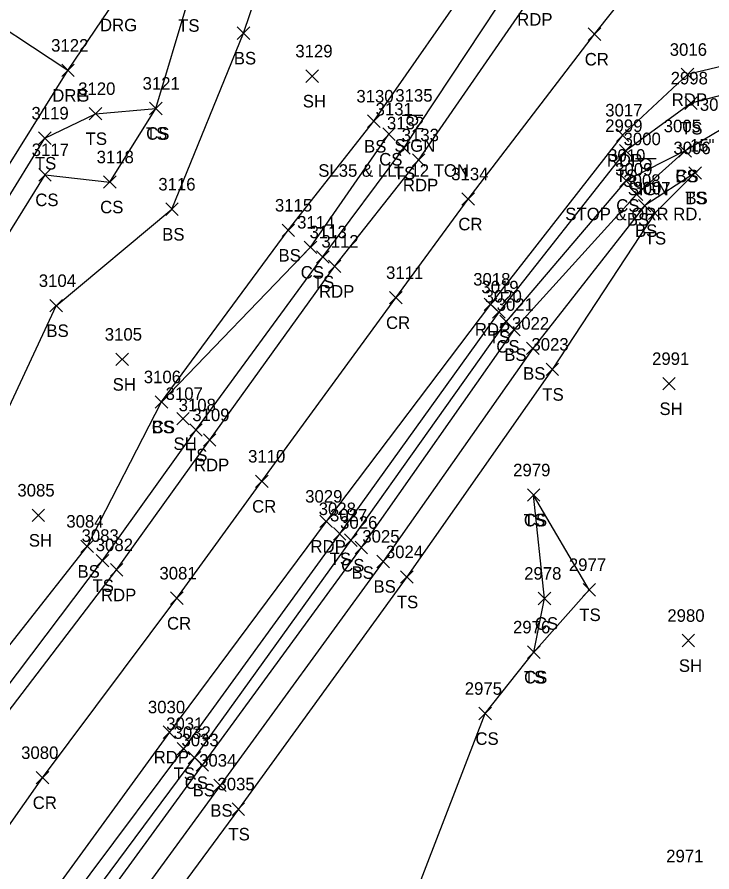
# Model space of a CAD drawing. Extents: x 1520648 to 1523413, y 732854 to 735518.
# Drawn here: x 1521785.1 to 1521896.1, y 733315.9 to 733452.5 of the extents above; entities that cross this region are included whole.
import ezdxf

# ---------------------------------------------------------------- set-up
doc = ezdxf.new("R2010")
doc.units = 0
for name, color, linetype in [('D_C', 7, 'Continuous'), ('L_A', 7, 'Continuous'), ('L_I', 7, 'Continuous'), ('L_TIC', 7, 'Continuous'), ('LELB', 7, 'Continuous'), ('P_A', 7, 'Continuous'), ('P_I', 7, 'Continuous'), ('P_TIC', 7, 'Continuous'), ('PET', 7, 'Continuous'), ('PRC', 7, 'Continuous'), ('R_A', 7, 'Continuous'), ('R_I', 7, 'Continuous'), ('R_TIC', 7, 'Continuous'), ('RDG', 7, 'Continuous'), ('RDP', 7, 'Continuous'), ('S_A', 7, 'Continuous'), ('S_C', 7, 'Continuous'), ('S_I', 7, 'Continuous'), ('SSGN', 7, 'Continuous')]:
    doc.layers.add(name, color=color, linetype=linetype)

msp = doc.modelspace()

# ---------------------------------------------------------------- linework, layer by layer
at = {"layer": 'L_TIC'}
for points in [[(1521820.29, 733448.95), (1521822.29, 733450.95)], [(1521822.29, 733448.95), (1521820.29, 733450.95)], [(1521831.26, 733442.08), (1521833.26, 733444.08)], [(1521833.26, 733442.08), (1521831.26, 733444.08)], [(1521891.77, 733437.76), (1521893.77, 733439.76)], [(1521893.77, 733437.76), (1521891.77, 733439.76)], [(1521796.65, 733436.08), (1521798.65, 733438.08)], [(1521798.65, 733436.08), (1521796.65, 733438.08)], [(1521806.29, 733436.92), (1521808.29, 733438.92)], [(1521808.29, 733436.92), (1521806.29, 733438.92)], [(1521806.29, 733436.92), (1521808.29, 733438.92)], [(1521808.29, 733436.92), (1521806.29, 733438.92)], [(1521841.09, 733434.87), (1521843.09, 733436.87)], [(1521843.09, 733434.87), (1521841.09, 733436.87)], [(1521788.55, 733432.16), (1521790.55, 733434.16)], [(1521790.55, 733432.16), (1521788.55, 733434.16)], [(1521843.51, 733432.8), (1521845.51, 733434.8)], [(1521845.51, 733432.8), (1521843.51, 733434.8)], [(1521845.88, 733430.59), (1521847.88, 733432.59)], [(1521847.88, 733430.59), (1521845.88, 733432.59)], [(1521881.33, 733430.16), (1521883.33, 733432.16)], [(1521883.33, 733430.16), (1521881.33, 733432.16)], [(1521890.82, 733430.12), (1521892.82, 733432.12)], [(1521892.82, 733430.12), (1521890.82, 733432.12)], [(1521890.82, 733430.12), (1521892.82, 733432.12)], [(1521892.82, 733430.12), (1521890.82, 733432.12)], [(1521788.58, 733426.31), (1521790.58, 733428.31)], [(1521790.58, 733426.31), (1521788.58, 733428.31)], [(1521892.42, 733426.61), (1521894.42, 733428.61)], [(1521894.42, 733426.61), (1521892.42, 733428.61)], [(1521892.42, 733426.61), (1521894.42, 733428.61)], [(1521894.42, 733426.61), (1521892.42, 733428.61)], [(1521798.94, 733425.16), (1521800.94, 733427.16)], [(1521800.94, 733425.16), (1521798.94, 733427.16)], [(1521881.38, 733425.41), (1521883.38, 733427.41)], [(1521883.38, 733425.41), (1521881.38, 733427.41)], [(1521883.07, 733423.19), (1521885.07, 733425.19)], [(1521885.07, 733423.19), (1521883.07, 733425.19)], [(1521884.37, 733421.39), (1521886.37, 733423.39)], [(1521886.37, 733421.39), (1521884.37, 733423.39)], [(1521808.85, 733420.81), (1521810.85, 733422.81)], [(1521810.85, 733420.81), (1521808.85, 733422.81)], [(1521885.97, 733420.18), (1521887.97, 733422.18)], [(1521887.97, 733420.18), (1521885.97, 733422.18)], [(1521827.43, 733417.45), (1521829.43, 733419.45)], [(1521829.43, 733417.45), (1521827.43, 733419.45)], [(1521830.98, 733414.73), (1521832.98, 733416.73)], [(1521832.98, 733414.73), (1521830.98, 733416.73)], [(1521832.96, 733413.18), (1521834.96, 733415.18)], [(1521834.96, 733413.18), (1521832.96, 733415.18)], [(1521790.35, 733405.4), (1521792.35, 733407.4)], [(1521792.35, 733405.4), (1521790.35, 733407.4)], [(1521861.06, 733404.38), (1521863.06, 733406.38)], [(1521863.06, 733404.38), (1521861.06, 733406.38)], [(1521862.22, 733402.9), (1521864.22, 733404.9)], [(1521864.22, 733402.9), (1521862.22, 733404.9)], [(1521863.49, 733401.58), (1521865.49, 733403.58)], [(1521865.49, 733401.58), (1521863.49, 733403.58)], [(1521866.5, 733398.58), (1521868.5, 733400.58)], [(1521868.5, 733398.58), (1521866.5, 733400.58)], [(1521800.89, 733396.82), (1521802.89, 733398.82)], [(1521802.89, 733396.82), (1521800.89, 733398.82)], [(1521869.61, 733395.22), (1521871.61, 733397.22)], [(1521871.61, 733395.22), (1521869.61, 733397.22)], [(1521888.24, 733392.93), (1521890.24, 733394.93)], [(1521890.24, 733392.93), (1521888.24, 733394.93)], [(1521807.18, 733390.02), (1521809.18, 733392.02)], [(1521809.18, 733390.02), (1521807.18, 733392.02)], [(1521807.18, 733390.02), (1521809.18, 733392.02)], [(1521809.18, 733390.02), (1521807.18, 733392.02)], [(1521810.61, 733387.35), (1521812.61, 733389.35)], [(1521812.61, 733387.35), (1521810.61, 733389.35)], [(1521812.69, 733385.53), (1521814.69, 733387.53)], [(1521814.69, 733385.53), (1521812.69, 733387.53)], [(1521866.62, 733375.14), (1521868.62, 733377.14)], [(1521868.62, 733375.14), (1521866.62, 733377.14)], [(1521866.62, 733375.14), (1521868.62, 733377.14)], [(1521868.62, 733375.14), (1521866.62, 733377.14)], [(1521787.5, 733371.91), (1521789.5, 733373.91)], [(1521789.5, 733371.91), (1521787.5, 733373.91)], [(1521835.63, 733368.94), (1521837.63, 733370.94)], [(1521837.63, 733368.94), (1521835.63, 733370.94)], [(1521837.43, 733367.93), (1521839.43, 733369.93)], [(1521839.43, 733367.93), (1521837.43, 733369.93)], [(1521795.31, 733366.94), (1521797.31, 733368.94)], [(1521797.31, 733366.94), (1521795.31, 733368.94)], [(1521839.1, 733366.76), (1521841.1, 733368.76)], [(1521841.1, 733366.76), (1521839.1, 733368.76)], [(1521797.75, 733364.67), (1521799.75, 733366.67)], [(1521799.75, 733364.67), (1521797.75, 733366.67)], [(1521842.6, 733364.54), (1521844.6, 733366.54)], [(1521844.6, 733364.54), (1521842.6, 733366.54)], [(1521846.36, 733362.06), (1521848.36, 733364.06)], [(1521848.36, 733362.06), (1521846.36, 733364.06)], [(1521875.51, 733360.01), (1521877.51, 733362.01)], [(1521877.51, 733360.01), (1521875.51, 733362.01)], [(1521868.37, 733358.62), (1521870.37, 733360.62)], [(1521870.37, 733358.62), (1521868.37, 733360.62)], [(1521891.33, 733351.89), (1521893.33, 733353.89)], [(1521893.33, 733351.89), (1521891.33, 733353.89)], [(1521866.65, 733350.04), (1521868.65, 733352.04)], [(1521868.65, 733350.04), (1521866.65, 733352.04)], [(1521866.65, 733350.04), (1521868.65, 733352.04)], [(1521868.65, 733350.04), (1521866.65, 733352.04)], [(1521858.88, 733340.23), (1521860.88, 733342.23)], [(1521860.88, 733340.23), (1521858.88, 733342.23)], [(1521810.7, 733334.61), (1521812.7, 733336.61)], [(1521812.7, 733334.61), (1521810.7, 733336.61)], [(1521812.45, 733333.19), (1521814.45, 733335.19)], [(1521814.45, 733333.19), (1521812.45, 733335.19)], [(1521813.7, 733332), (1521815.7, 733334)], [(1521815.7, 733332), (1521813.7, 733334)], [(1521816.53, 733328.75), (1521818.53, 733330.75)], [(1521818.53, 733328.75), (1521816.53, 733330.75)], [(1521819.46, 733324.96), (1521821.46, 733326.96)], [(1521821.46, 733324.96), (1521819.46, 733326.96)]]:
    msp.add_lwpolyline(points, dxfattribs=at)
at = {"layer": 'LELB'}
for points in [[(1521759.01, 733350.84), (1521778.84, 733379.61), (1521791.35, 733406.4), (1521809.85, 733421.81), (1521821.29, 733449.95), (1521829.42, 733474.04), (1521816.98, 733499.02), (1521803.61, 733521.39), (1521760.13, 733541.49), (1521753.02, 733560.88), (1521736.69, 733577.42), (1521715.31, 733596.64)], [(1521749.24, 733355.76), (1521768.57, 733384.54), (1521778.63, 733397.02), (1521778.03, 733414.53), (1521789.55, 733433.16), (1521797.65, 733437.08), (1521807.29, 733437.92), (1521812.43, 733455.17), (1521816.31, 733477.33), (1521808.57, 733496.49), (1521793.28, 733514.64), (1521756.08, 733535.47), (1521746.24, 733557.11), (1521726.08, 733570.55), (1521703.63, 733583.19)], [(1521759.15, 733317.04), (1521772.09, 733331.62), (1521778.42, 733338.78), (1521798.75, 733365.67), (1521813.69, 733386.53), (1521833.96, 733414.18), (1521846.88, 733431.59), (1521864.41, 733458.07), (1521876.44, 733476.09), (1521887.28, 733496.86), (1521887.61, 733499.46), (1521888.35, 733509.55), (1521886.12, 733515.05), (1521875.14, 733547.35)], [(1521745.22, 733320.11), (1521742.07, 733329.87), (1521753.4, 733325.06), (1521769.53, 733333.34), (1521775.51, 733341.53), (1521796.31, 733367.94), (1521808.18, 733391.02), (1521828.43, 733418.45), (1521842.09, 733435.87), (1521859.18, 733460.44), (1521868.01, 733480.25), (1521878.13, 733498.03), (1521883.64, 733498.41), (1521879.84, 733511.18), (1521868.37, 733545.03)], [(1521968.22, 732870.86), (1521967.33, 732923.17), (1521965.89, 732967.63), (1521966.81, 733022.76), (1521968.92, 733067.53), (1521967.76, 733107.86), (1521967.59, 733152.46), (1521963.2, 733196.23), (1521957.56, 733240.65), (1521950.49, 733284.14), (1521942.81, 733326), (1521935.57, 733358.13), (1521922.67, 733395.52), (1521912.69, 733424.26), (1521908.68, 733436.25), (1521904.92, 733439.85), (1521900.99, 733440.9), (1521892.77, 733438.76), (1521882.33, 733431.16), (1521862.06, 733405.38), (1521836.63, 733369.94), (1521811.7, 733335.61), (1521781.71, 733295.53)], [(1521778.63, 733397.02), (1521780.75, 733413.12), (1521789.58, 733427.31), (1521799.94, 733426.16), (1521807.29, 733437.92)], [(1521949.65, 732892.14), (1521943.39, 732922.28), (1521945.76, 732969.81), (1521946.37, 733022.02), (1521949.39, 733069.39), (1521949.05, 733107.25), (1521954.07, 733151.48), (1521948.09, 733195.39), (1521946.43, 733238.1), (1521937.33, 733283.09), (1521933.08, 733323.42), (1521926.44, 733357.1), (1521915.28, 733394.28), (1521907.45, 733416.63), (1521900.78, 733431.27), (1521903.17, 733437.88), (1521902.02, 733437.98), (1521897.59, 733434.54), (1521891.82, 733431.12), (1521884.07, 733424.19), (1521864.49, 733402.58), (1521840.1, 733367.76), (1521814.7, 733333), (1521785.26, 733292.58)], [(1521808.18, 733391.02), (1521831.98, 733415.73), (1521844.51, 733433.8)], [(1521891.82, 733431.12), (1521882.38, 733426.41), (1521863.22, 733403.9), (1521838.43, 733368.93), (1521813.45, 733334.19), (1521783.62, 733294.05)], [(1521893.42, 733427.61), (1521885.37, 733422.39), (1521867.5, 733399.58), (1521843.6, 733365.54), (1521817.53, 733329.75), (1521788.72, 733290.22)], [(1521893.42, 733427.61), (1521886.97, 733421.18), (1521870.61, 733396.22), (1521847.36, 733363.06), (1521820.46, 733325.96), (1521793.78, 733289.79)], [(1521841.16, 733284.19), (1521847.31, 733308.65), (1521859.88, 733341.23), (1521867.65, 733351.04), (1521869.37, 733359.62), (1521867.62, 733376.14)], [(1521867.65, 733351.04), (1521876.51, 733361.01), (1521867.62, 733376.14)]]:
    msp.add_lwpolyline(points, dxfattribs=at)
at = {"layer": 'P_TIC'}
for points in [[(1521876.35, 733448.78), (1521878.35, 733450.78)], [(1521878.35, 733448.78), (1521876.35, 733450.78)], [(1521891.19, 733442.33), (1521893.19, 733444.33)], [(1521893.19, 733442.33), (1521891.19, 733444.33)], [(1521880.84, 733432.64), (1521882.84, 733434.64)], [(1521882.84, 733432.64), (1521880.84, 733434.64)], [(1521848.25, 733428.67), (1521850.25, 733430.67)], [(1521850.25, 733428.67), (1521848.25, 733430.67)], [(1521856.16, 733422.44), (1521858.16, 733424.44)], [(1521858.16, 733422.44), (1521856.16, 733424.44)], [(1521834.85, 733411.69), (1521836.85, 733413.69)], [(1521836.85, 733411.69), (1521834.85, 733413.69)], [(1521844.61, 733406.68), (1521846.61, 733408.68)], [(1521846.61, 733406.68), (1521844.61, 733408.68)], [(1521859.74, 733405.62), (1521861.74, 733407.62)], [(1521861.74, 733405.62), (1521859.74, 733407.62)], [(1521814.88, 733383.95), (1521816.88, 733385.95)], [(1521816.88, 733383.95), (1521814.88, 733385.95)], [(1521823.22, 733377.34), (1521825.22, 733379.34)], [(1521825.22, 733377.34), (1521823.22, 733379.34)], [(1521833.48, 733370.94), (1521835.48, 733372.94)], [(1521835.48, 733370.94), (1521833.48, 733372.94)], [(1521800.02, 733363.18), (1521802.02, 733365.18)], [(1521802.02, 733363.18), (1521800.02, 733365.18)], [(1521809.63, 733358.66), (1521811.63, 733360.66)], [(1521811.63, 733358.66), (1521809.63, 733360.66)], [(1521808.44, 733337.27), (1521810.44, 733339.27)], [(1521810.44, 733337.27), (1521808.44, 733339.27)], [(1521788.18, 733329.98), (1521790.18, 733331.98)], [(1521790.18, 733329.98), (1521788.18, 733331.98)]]:
    msp.add_lwpolyline(points, dxfattribs=at)
at = {"layer": 'PET'}
for points in [[(1521760.79, 733310.27), (1521766, 733317.77), (1521780.4, 733337.26), (1521801.02, 733364.18), (1521815.88, 733384.95), (1521835.85, 733412.69), (1521849.25, 733429.67), (1521867.5, 733456.15), (1521880.02, 733475.39), (1521889.73, 733495.65), (1521892.95, 733514.59)], [(1521917.02, 733438.97), (1521910.27, 733443.9), (1521901.79, 733445.62), (1521892.19, 733443.33), (1521881.84, 733433.64), (1521860.74, 733406.62), (1521834.48, 733371.94), (1521809.44, 733338.27), (1521779.48, 733297.11)]]:
    msp.add_lwpolyline(points, dxfattribs=at)
at = {"layer": 'PRC'}
msp.add_lwpolyline([(1521770.1, 733303.86), (1521789.18, 733330.98), (1521810.63, 733359.66), (1521824.22, 733378.34), (1521845.61, 733407.68), (1521857.16, 733423.44), (1521877.35, 733449.78), (1521891.97, 733468.24), (1521903.82, 733481.12)], dxfattribs=at)
at = {"layer": 'R_TIC'}
for points in [[(1521792.24, 733443), (1521794.24, 733445)], [(1521794.24, 733443), (1521792.24, 733445)], [(1521792.24, 733443), (1521794.24, 733445)], [(1521794.24, 733443), (1521792.24, 733445)]]:
    msp.add_lwpolyline(points, dxfattribs=at)
at = {"layer": 'RDG'}
msp.add_lwpolyline([(1521793.24, 733444), (1521800.86, 733455.25), (1521800.56, 733464.07), (1521801.18, 733479.7), (1521792.16, 733500.04), (1521784.55, 733509.91), (1521756.08, 733535.47), (1521735.24, 733549.65), (1521720.37, 733558.44), (1521694.61, 733570.42), (1521676.51, 733543.41)], dxfattribs=at)
at = {"layer": 'RDP'}
msp.add_lwpolyline([(1521766, 733317.77), (1521759.15, 733317.04), (1521747.32, 733317.78), (1521745.22, 733320.11), (1521730.68, 733334.25), (1521725.41, 733346.47), (1521724.94, 733355.82), (1521726.82, 733367.33), (1521739.16, 733357.93), (1521759.27, 733389.99), (1521775.49, 733415.6), (1521793.24, 733444), (1521776.4, 733455.04), (1521760.93, 733467.25), (1521758.1, 733472.44), (1521748.94, 733490.42), (1521732.1, 733509.37), (1521713.69, 733523.9), (1521690.78, 733537.56)], dxfattribs=at)
at = {"layer": 'SSGN'}
for p, q in [((1521846.6, 733436.85), (1521849.93, 733436.85)), ((1521848.24, 733436.02), (1521848.24, 733436.02)), ((1521883.87, 733429.9), (1521887.2, 733429.9)), ((1521885.52, 733429.07), (1521885.52, 733429.07))]:
    msp.add_line(p, q, dxfattribs=at)
for centre in [(1521848.24, 733436.02), (1521885.52, 733429.07)]:
    msp.add_circle(centre, 0.833, dxfattribs=at)

# ---------------------------------------------------------------- texts
at = {"layer": 'D_C'}
msp.add_text('15" CGMP POOR', height=2, dxfattribs=at).set_placement((1521892.59, 733431.03))
at = {"layer": 'L_A'}
for s, p in [('TS', (1521810.84, 733450.17)), ('BS', (1521819.73, 733444.95)), ('SH', (1521830.75, 733438.08)), ('TS', (1521891.18, 733433.76)), ('TS', (1521796.06, 733432.08)), ('TS', (1521805.69, 733432.92)), ('CS', (1521805.73, 733432.92)), ('BS', (1521840.53, 733430.87)), ('TS', (1521787.96, 733428.16)), ('CS', (1521842.95, 733428.8)), ('TS', (1521845.29, 733426.59)), ('TS', (1521880.74, 733426.16)), ('CS', (1521890.26, 733426.12)), ('BS', (1521890.26, 733426.12)), ('CS', (1521788.02, 733422.31)), ('TS', (1521891.83, 733422.61)), ('BS', (1521891.86, 733422.61)), ('CS', (1521798.38, 733421.16)), ('CS', (1521880.82, 733421.41)), ('BS', (1521882.51, 733419.19)), ('BS', (1521808.29, 733416.81)), ('BS', (1521883.81, 733417.39)), ('TS', (1521885.37, 733416.18)), ('BS', (1521826.87, 733413.45)), ('CS', (1521830.42, 733410.73)), ('TS', (1521832.36, 733409.18)), ('BS', (1521789.79, 733401.4)), ('TS', (1521860.47, 733400.38)), ('CS', (1521861.66, 733398.9)), ('BS', (1521862.93, 733397.58)), ('BS', (1521865.94, 733394.58)), ('SH', (1521800.38, 733392.82)), ('TS', (1521869.01, 733391.22)), ('SH', (1521887.72, 733388.93)), ('CS', (1521806.62, 733386.02)), ('BS', (1521806.62, 733386.02)), ('SH', (1521810.1, 733383.35)), ('TS', (1521812.1, 733381.53)), ('TS', (1521866.03, 733371.14)), ('CS', (1521866.06, 733371.14)), ('SH', (1521786.99, 733367.91)), ('TS', (1521835.04, 733364.94)), ('CS', (1521836.88, 733363.93)), ('BS', (1521794.76, 733362.94)), ('BS', (1521838.54, 733362.76)), ('TS', (1521797.16, 733360.67)), ('BS', (1521842.04, 733360.54)), ('TS', (1521845.77, 733358.06)), ('TS', (1521874.92, 733356.01)), ('CS', (1521867.82, 733354.62)), ('SH', (1521890.82, 733347.89)), ('TS', (1521866.06, 733346.04)), ('CS', (1521866.09, 733346.04)), ('CS', (1521858.32, 733336.23)), ('TS', (1521810.11, 733330.61)), ('CS', (1521811.89, 733329.19)), ('BS', (1521813.15, 733328)), ('BS', (1521815.97, 733324.75)), ('TS', (1521818.87, 733320.96))]:
    msp.add_text(s, height=2, dxfattribs=at).set_placement(p)
at = {"layer": 'L_I'}
for s, p in [('3129', (1521829.56, 733446.08)), ('2998', (1521889.51, 733441.76)), ('3120', (1521794.87, 733440.08)), ('3121', (1521805.16, 733440.92)), ('3121', (1521805.16, 733440.92)), ('3130', (1521839.31, 733438.87)), ('3004', (1521894.17, 733437.54)), ('3119', (1521787.41, 733436.16)), ('3131', (1521842.38, 733436.8)), ('3132', (1521844.19, 733434.59)), ('2999', (1521879.06, 733434.16)), ('3005', (1521888.4, 733434.12)), ('3005', (1521888.4, 733434.12)), ('3006', (1521889.95, 733430.61)), ('3006', (1521889.95, 733430.61)), ('3117', (1521787.45, 733430.31)), ('3118', (1521797.82, 733429.16)), ('3010', (1521879.52, 733429.41)), ('3009', (1521880.65, 733427.19)), ('3008', (1521881.95, 733425.39)), ('3116', (1521807.67, 733424.81)), ('3007', (1521883.55, 733424.18)), ('3115', (1521826.3, 733421.45)), ('3114', (1521829.85, 733418.73)), ('3113', (1521831.83, 733417.18)), ('3104', (1521788.58, 733409.4)), ('3019', (1521859.28, 733408.38)), ('3020', (1521859.79, 733406.9)), ('3021', (1521861.72, 733405.58)), ('3022', (1521864.16, 733402.58)), ('3105', (1521799.12, 733400.82)), ('3023', (1521867.27, 733399.22)), ('2991', (1521886.54, 733396.93)), ('3106', (1521805.35, 733394.02)), ('3106', (1521805.35, 733394.02)), ('3107', (1521808.84, 733391.35)), ('3108', (1521810.92, 733389.53)), ('2979', (1521864.35, 733379.14)), ('2979', (1521864.35, 733379.14)), ('3085', (1521785.16, 733375.91)), ('3028', (1521833.29, 733372.94)), ('3027', (1521835.1, 733371.93)), ('3084', (1521792.98, 733370.94)), ('3026', (1521836.71, 733370.76)), ('3083', (1521795.41, 733368.67)), ('3025', (1521840.26, 733368.54)), ('3024', (1521844.02, 733366.06)), ('2977', (1521873.25, 733364.01)), ('2978', (1521866.11, 733362.62)), ('2980', (1521888.98, 733355.89)), ('2976', (1521864.33, 733354.04)), ('2976', (1521864.33, 733354.04)), ('2975', (1521856.62, 733344.23)), ('3031', (1521808.93, 733338.61)), ('3032', (1521810.11, 733337.19)), ('3033', (1521811.37, 733336)), ('3034', (1521814.19, 733332.75)), ('3035', (1521817.12, 733328.96)), ('2971', (1521888.8, 733317.47))]:
    msp.add_text(s, height=2, dxfattribs=at).set_placement(p)
at = {"layer": 'P_A'}
for s, p in [('RDP', (1521864.99, 733451.15)), ('CR', (1521875.78, 733444.78)), ('RDP', (1521889.68, 733438.33)), ('RDP', (1521879.32, 733428.64)), ('RDP', (1521846.74, 733424.67)), ('CR', (1521855.59, 733418.44)), ('RDP', (1521833.34, 733407.69)), ('CR', (1521844.04, 733402.68)), ('RDP', (1521858.23, 733401.62)), ('RDP', (1521813.36, 733379.95)), ('CR', (1521822.65, 733373.34)), ('RDP', (1521831.97, 733366.94)), ('RDP', (1521798.51, 733359.18)), ('CR', (1521809.06, 733354.66)), ('RDP', (1521806.93, 733333.27)), ('CR', (1521787.61, 733325.98))]:
    msp.add_text(s, height=2, dxfattribs=at).set_placement(p)
at = {"layer": 'P_I'}
for s, p in [('3016', (1521889.36, 733446.33)), ('3017', (1521879.06, 733436.64)), ('3133', (1521846.55, 733432.67)), ('3134', (1521854.46, 733426.44)), ('3112', (1521833.72, 733415.69)), ('3111', (1521844.05, 733410.68)), ('3018', (1521857.97, 733409.62)), ('3109', (1521813.1, 733387.95)), ('3110', (1521822.01, 733381.34)), ('3029', (1521831.13, 733374.94)), ('3082', (1521797.68, 733367.18)), ('3081', (1521807.85, 733362.66)), ('3030', (1521806.01, 733341.27)), ('3080', (1521785.76, 733333.98))]:
    msp.add_text(s, height=2, dxfattribs=at).set_placement(p)
at = {"layer": 'R_A'}
for s, p in [('DRG', (1521798.35, 733450.25)), ('DRG', (1521790.73, 733439)), ('DRP', (1521790.73, 733439))]:
    msp.add_text(s, height=2, dxfattribs=at).set_placement(p)
at = {"layer": 'R_I'}
msp.add_text('3122', height=2, dxfattribs=at).set_placement((1521790.55, 733447))
msp.add_text('3122', height=2, dxfattribs=at).set_placement((1521790.55, 733447))
at = {"layer": 'S_A'}
for p in [(1521845.38, 733431), (1521882.66, 733424.05)]:
    msp.add_text('SIGN', height=2, dxfattribs=at).set_placement(p)
at = {"layer": 'S_C'}
for s, p in [('SL35 & LLL 12 TON', (1521833.22, 733427)), ('STOP & ORR RD.', (1521872.68, 733420.05))]:
    msp.add_text(s, height=2, dxfattribs=at).set_placement(p)
at = {"layer": 'S_I'}
for s, p in [('3135', (1521845.53, 733439)), ('3000', (1521881.99, 733432.05))]:
    msp.add_text(s, height=2, dxfattribs=at).set_placement(p)

doc.saveas('drawing.dxf')
